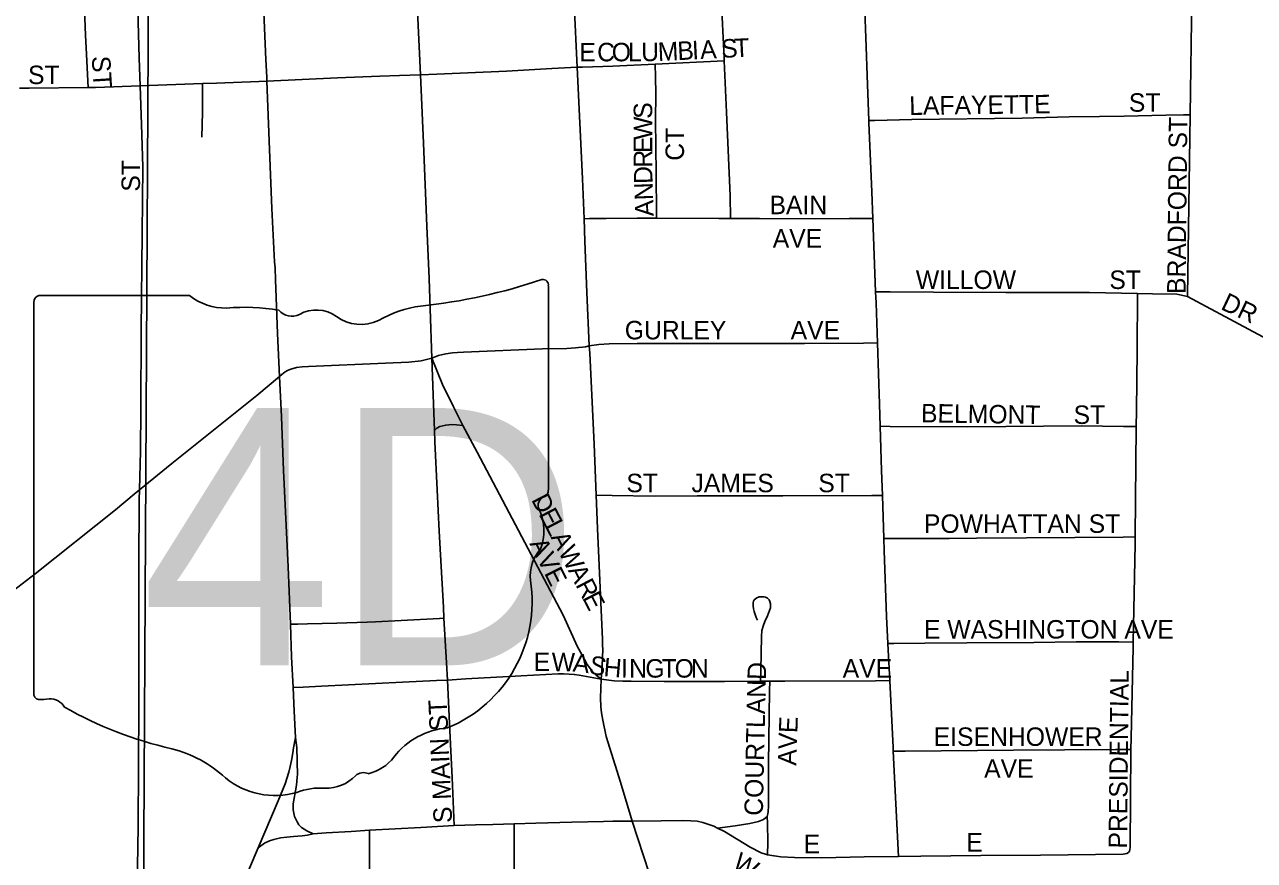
# Model space of a CAD drawing. Extents: x -97 to 34, y -21 to 22.
# Drawn here: x 5.533 to 6.163, y 18.994 to 19.422 of the extents above; entities that cross this region are included whole.
import ezdxf

# ---------------------------------------------------------------- set-up
doc = ezdxf.new("R2010")
doc.units = 0
for name, color, linetype in [('GM_X_City_Street', 7, 'Continuous'), ('GM_X_City_Street_Text', 7, 'Continuous'), ('GM_X_Section', 7, 'Continuous'), ('GM_X_State_Location', 7, 'Continuous'), ('GM_X_State_Route', 7, 'Continuous'), ('GM_X_State_Shield', 7, 'Continuous')]:
    doc.layers.add(name, color=color, linetype=linetype)

msp = doc.modelspace()

# ---------------------------------------------------------------- linework, layer by layer
at = {"layer": 'GM_X_City_Street'}
for points in [[(5.56519, 19.38978), (5.5642, 19.41012), (5.56376, 19.41668), (5.56336, 19.42539), (5.56266, 19.44389), (5.56246, 19.45285)], [(5.59185, 19.39064), (5.59135, 19.40487), (5.59057, 19.42962), (5.5894, 19.45308)], [(5.89109, 19.40348), (5.89103, 19.40499), (5.88954, 19.4362)], [(5.96306, 19.43384), (5.96394, 19.41059), (5.96445, 19.39593), (5.96525, 19.37289)], [(6.1299, 19.37581), (6.13076, 19.43609)], [(5.7355, 19.39632), (5.73394, 19.42898)], [(5.81579, 19.40021), (5.81843, 19.40029), (5.83406, 19.40077), (5.85574, 19.40184)], [(5.85574, 19.40184), (5.89109, 19.40348)], [(5.85648, 19.32277), (5.85648, 19.32516), (5.85621, 19.34582), (5.85587, 19.37305), (5.8561, 19.38656), (5.85598, 19.39532), (5.85574, 19.40184)], [(5.89425, 19.32267), (5.89413, 19.33422), (5.89234, 19.37717), (5.89109, 19.40348)], [(5.65673, 19.39306), (5.6929, 19.39476), (5.71459, 19.39557), (5.7247, 19.39592), (5.7355, 19.39632)], [(5.52997, 19.38945), (5.53485, 19.38947), (5.56519, 19.38978)], [(5.56519, 19.38978), (5.56896, 19.38982), (5.59185, 19.39064)], [(5.59144, 19.1837), (5.59202, 19.20337), (5.59206, 19.22506), (5.59237, 19.2654), (5.59289, 19.31503), (5.59308, 19.34916), (5.59253, 19.37083), (5.59185, 19.39064)], [(5.59185, 19.39064), (5.62367, 19.39178)], [(5.62367, 19.39178), (5.62369, 19.3883), (5.62372, 19.37719), (5.62339, 19.36436)], [(5.62367, 19.39178), (5.63092, 19.39204), (5.65256, 19.39287), (5.65673, 19.39306)], [(5.96525, 19.37289), (5.96837, 19.37297), (5.98725, 19.37341), (6.04383, 19.37409), (6.06782, 19.37477), (6.08337, 19.37489), (6.09614, 19.37517), (6.11745, 19.37561), (6.12655, 19.37576), (6.1299, 19.37581)], [(6.12857, 19.28265), (6.1299, 19.37581)], [(5.96525, 19.37289), (5.96529, 19.37173), (5.96669, 19.3363), (5.96723, 19.32266)], [(5.8194, 19.32247), (5.82211, 19.32272), (5.83062, 19.32264), (5.84648, 19.32279), (5.85648, 19.32277)], [(5.85648, 19.32277), (5.88829, 19.32269), (5.89425, 19.32267)], [(5.89425, 19.32267), (5.90928, 19.32262), (5.93752, 19.32254), (5.95511, 19.32268), (5.96068, 19.32274), (5.96723, 19.32266)], [(5.96723, 19.32266), (5.96872, 19.28504)], [(5.96872, 19.28504), (5.97614, 19.28508), (5.99836, 19.28496), (6.03538, 19.28476), (6.07831, 19.28478), (6.10291, 19.28417)], [(5.96872, 19.28504), (5.96894, 19.27942), (5.96967, 19.25889)], [(6.10231, 19.21604), (6.10245, 19.22412), (6.1027, 19.25519), (6.10291, 19.28417)], [(6.10291, 19.28417), (6.11054, 19.28402), (6.12307, 19.28387), (6.12857, 19.28265)], [(6.12857, 19.28265), (6.15986, 19.26603), (6.18723, 19.25123)], [(5.74132, 19.25111), (5.74462, 19.2525), (5.74838, 19.25332), (5.7519, 19.25384), (5.75447, 19.25401), (5.75753, 19.25423), (5.79795, 19.25586), (5.81048, 19.2561), (5.81496, 19.25638), (5.81646, 19.25653), (5.81844, 19.25672), (5.82007, 19.25694), (5.82195, 19.25734)], [(5.82195, 19.25734), (5.82683, 19.25809), (5.83223, 19.25843), (5.8465, 19.25857), (5.87142, 19.25858), (5.90187, 19.25859), (5.93219, 19.25868), (5.96246, 19.25885), (5.96967, 19.25889)], [(5.96967, 19.25889), (5.97078, 19.2275), (5.97109, 19.21618)], [(5.74259, 19.21403), (5.74197, 19.23231), (5.74132, 19.25111)], [(5.75723, 19.21662), (5.7524, 19.22616), (5.74671, 19.23756), (5.74132, 19.25111)], [(5.74259, 19.21403), (5.74389, 19.21525), (5.74541, 19.21605), (5.74843, 19.21677), (5.75153, 19.21706), (5.75384, 19.21698), (5.75723, 19.21662)], [(5.74743, 19.11781), (5.7472, 19.12355), (5.74569, 19.15037), (5.7451, 19.16248), (5.74407, 19.18357), (5.74287, 19.20823), (5.74259, 19.21403)], [(5.82802, 19.0866), (5.82527, 19.0888), (5.82363, 19.09044), (5.82081, 19.0941), (5.81807, 19.09928), (5.81598, 19.10321), (5.80851, 19.11931), (5.76444, 19.2029), (5.75723, 19.21662)], [(5.97109, 19.21618), (5.97618, 19.21616), (6.01597, 19.21595), (6.07427, 19.21634), (6.09571, 19.216), (6.10231, 19.21604)], [(5.97109, 19.21618), (5.9717, 19.19351), (5.97216, 19.18074)], [(6.10174, 19.15949), (6.10231, 19.21604)], [(5.58975, 18.8933), (5.59013, 18.93041), (5.59013, 18.96145), (5.59029, 18.9801), (5.59084, 19.01111), (5.59091, 19.04212), (5.59113, 19.07316), (5.59112, 19.11343), (5.59118, 19.14442), (5.59129, 19.17858), (5.59144, 19.1837)], [(5.82554, 19.18085), (5.83373, 19.18074), (5.85545, 19.18044), (5.8773, 19.1805), (5.9212, 19.18061), (5.96681, 19.18072), (5.97216, 19.18074)], [(5.97216, 19.18074), (5.97294, 19.15861)], [(5.97294, 19.15861), (5.97872, 19.15864), (5.9972, 19.15872), (6.00636, 19.15867), (6.02049, 19.15879), (6.04599, 19.15901), (6.09553, 19.15943), (6.10174, 19.15949)], [(5.97294, 19.15861), (5.97316, 19.15245), (5.9743, 19.11871), (5.97499, 19.10482)], [(6.10071, 19.10558), (6.10171, 19.15583), (6.10174, 19.15949)], [(5.90972, 19.08548), (5.90992, 19.09118), (5.91022, 19.10853), (5.91042, 19.11148), (5.91124, 19.1143), (5.91193, 19.1161), (5.91326, 19.11901), (5.9144, 19.12182), (5.91478, 19.12315), (5.9149, 19.12403), (5.91482, 19.12524), (5.91454, 19.12631), (5.91417, 19.12719), (5.91337, 19.1281), (5.91227, 19.12864), (5.91146, 19.12879), (5.91015, 19.12885), (5.90905, 19.12871), (5.90775, 19.12825), (5.90709, 19.12778), (5.9065, 19.1272), (5.90615, 19.12655), (5.90593, 19.12579), (5.90589, 19.12425), (5.90616, 19.12271), (5.90652, 19.12122), (5.90698, 19.11966), (5.90755, 19.11817), (5.90821, 19.11684)], [(5.66876, 19.1147), (5.67263, 19.11481), (5.67757, 19.11495), (5.69261, 19.11533), (5.70818, 19.11579), (5.71241, 19.11598), (5.72554, 19.11669), (5.74518, 19.1177), (5.74743, 19.11781)], [(5.74922, 19.08609), (5.74871, 19.09493), (5.74743, 19.11781)], [(5.97499, 19.10482), (5.978, 19.10485), (5.99396, 19.10498), (6.01541, 19.10519), (6.04983, 19.10538), (6.0715, 19.10565), (6.09343, 19.10564), (6.10071, 19.10558)], [(5.97499, 19.10482), (5.97514, 19.1017), (5.97593, 19.08583)], [(6.09956, 19.05046), (6.09961, 19.05646), (6.10066, 19.10284), (6.10071, 19.10558)], [(5.67018, 19.08229), (5.67538, 19.08255), (5.68471, 19.08302), (5.72624, 19.0851), (5.74358, 19.08594), (5.74922, 19.08609)], [(5.74922, 19.08609), (5.75862, 19.08679), (5.78699, 19.08831), (5.80601, 19.08926), (5.80876, 19.08924), (5.81158, 19.08921), (5.81426, 19.08903), (5.81679, 19.08858), (5.82802, 19.0866)], [(5.75266, 19.01158), (5.7517, 19.03623), (5.75093, 19.04969), (5.75032, 19.06388), (5.74922, 19.08609)], [(5.82802, 19.0866), (5.8347, 19.08579), (5.83922, 19.0855), (5.8435, 19.08548), (5.86034, 19.08544), (5.89126, 19.08543), (5.90972, 19.08548)], [(5.90972, 19.08548), (5.91447, 19.0855)], [(5.91305, 19.01622), (5.91353, 19.01759), (5.91372, 19.01876), (5.91376, 19.02148), (5.91387, 19.04317), (5.9144, 19.08067), (5.91447, 19.0855)], [(5.91447, 19.0855), (5.92214, 19.08553), (5.96861, 19.08578), (5.97593, 19.08583)], [(5.97593, 19.08583), (5.97763, 19.05163), (5.97773, 19.04969)], [(5.97773, 19.04969), (5.98388, 19.04975), (6.03929, 19.05023), (6.09162, 19.05055), (6.0947, 19.05051), (6.09956, 19.05046)], [(5.97773, 19.04969), (5.9805, 18.9957)], [(6.0983, 18.99774), (6.09876, 18.9984), (6.09905, 18.99929), (6.09917, 19.0003), (6.09956, 19.05046)], [(5.88769, 19.0103), (5.89667, 19.01148), (5.90418, 19.01263), (5.90862, 19.01356), (5.91133, 19.01471), (5.91305, 19.01622)], [(5.91334, 18.99662), (5.91344, 19.0029), (5.91325, 19.01286), (5.91305, 19.01622)], [(5.70943, 18.88967), (5.70942, 18.91883), (5.70936, 18.98514), (5.70929, 19.00356), (5.70936, 19.00915)], [(5.78232, 18.84388), (5.78273, 18.89006), (5.78335, 18.91997), (5.78339, 18.93672), (5.78344, 18.9592), (5.78347, 18.98194), (5.78344, 19.0038), (5.78338, 19.01248)], [(5.88769, 19.0103), (5.88585, 19.01123), (5.88018, 19.0131), (5.87718, 19.01378), (5.87398, 19.01407), (5.86971, 19.01416), (5.85886, 19.01403), (5.84391, 19.01387)], [(5.91334, 18.99662), (5.91278, 18.99671), (5.9101, 18.99765), (5.90438, 19.00042), (5.89126, 19.0085), (5.88769, 19.0103)], [(5.9805, 18.9957), (5.96289, 18.99558), (5.94118, 18.99508), (5.92716, 18.99524), (5.92014, 18.99557), (5.91668, 18.99601), (5.91334, 18.99662)], [(5.9805, 18.9957), (5.99195, 18.9959), (6.02255, 18.99616), (6.05317, 18.9964), (6.09561, 18.99691), (6.09647, 18.99699), (6.09741, 18.99719), (6.0983, 18.99774)]]:
    msp.add_lwpolyline(points, dxfattribs=at)
at = {"layer": 'GM_X_Section'}
for points in [[(4.59865, 19.47855), (5.59615, 19.47364), (5.59082, 18.47236), (4.59557, 18.47233)], [(5.59615, 19.47364), (6.60805, 19.46219), (6.59547, 18.46625), (5.59082, 18.47236)]]:
    msp.add_lwpolyline(points, close=True, dxfattribs=at)
at = {"layer": 'GM_X_State_Route'}
for points in [[(5.81579, 19.40021), (5.81426, 19.43276), (5.81368, 19.44493), (5.81305, 19.46133), (5.81178, 19.49422), (5.81007, 19.53664), (5.80859, 19.57918)], [(5.64841, 19.57304), (5.65021, 19.54453), (5.65196, 19.49769), (5.65352, 19.46651), (5.65397, 19.45497), (5.65413, 19.45102), (5.65492, 19.4323), (5.65622, 19.40416), (5.65663, 19.39506)], [(5.7355, 19.39632), (5.74385, 19.39671), (5.77947, 19.39823), (5.80271, 19.39949), (5.81579, 19.40021)], [(5.82883, 19.10163), (5.82881, 19.10422), (5.82878, 19.10697), (5.82625, 19.16379), (5.82554, 19.18085), (5.82444, 19.20711), (5.82223, 19.25365), (5.82195, 19.25734), (5.82075, 19.28483), (5.81976, 19.3111), (5.8194, 19.32247), (5.81849, 19.34306), (5.81579, 19.40021)], [(5.65663, 19.39506), (5.65673, 19.39306), (5.65802, 19.35803), (5.65931, 19.32772), (5.66071, 19.30046), (5.6609, 19.29743), (5.66111, 19.29131), (5.66157, 19.28214), (5.66213, 19.26381), (5.66316, 19.24175)], [(5.74132, 19.25111), (5.74041, 19.27633), (5.73985, 19.29189), (5.73874, 19.31883), (5.73698, 19.36137), (5.7355, 19.39632)], [(5.52685, 19.132), (5.53798, 19.14055), (5.57916, 19.17341), (5.58864, 19.18142), (5.59144, 19.1837), (5.60795, 19.19715), (5.62255, 19.20881), (5.65162, 19.23203), (5.66316, 19.24175), (5.66447, 19.24281), (5.66604, 19.24406), (5.66728, 19.24477), (5.66902, 19.24541), (5.67196, 19.24624), (5.67488, 19.2467), (5.67804, 19.24675), (5.7175, 19.24848), (5.72944, 19.24908), (5.73576, 19.24977), (5.74132, 19.25111)], [(5.66316, 19.24175), (5.66424, 19.22098), (5.66521, 19.19356), (5.66756, 19.14419), (5.66876, 19.1147), (5.66943, 19.09796), (5.67018, 19.08229), (5.67076, 19.07019), (5.67148, 19.05665)], [(5.82802, 19.0866), (5.8285, 19.09305), (5.82875, 19.09802), (5.82883, 19.10158), (5.82883, 19.10163)], [(5.84391, 19.01387), (5.8379, 19.03376), (5.83054, 19.05721), (5.82883, 19.06566), (5.82825, 19.06942), (5.82793, 19.0724), (5.8277, 19.07702), (5.82802, 19.0866)], [(5.67148, 19.05665), (5.67043, 19.05141), (5.67004, 19.04887), (5.66934, 19.04485), (5.66871, 19.04179), (5.66798, 19.03888), (5.66613, 19.03295), (5.66259, 19.02428), (5.6523, 19.00021)], [(5.67148, 19.05665), (5.67202, 19.05156), (5.67237, 19.03746), (5.67233, 19.03672), (5.67203, 19.03375), (5.67166, 19.0312), (5.67015, 19.02266), (5.6702, 19.01967), (5.67084, 19.01629), (5.67223, 19.01339), (5.67319, 19.01201), (5.67447, 19.01057), (5.67726, 19.0089), (5.68042, 19.00736)], [(5.68042, 19.00736), (5.68704, 19.00778), (5.69989, 19.00857), (5.70936, 19.00915), (5.73562, 19.01063), (5.75266, 19.01158), (5.76364, 19.0119), (5.77247, 19.01216), (5.78338, 19.01248), (5.79463, 19.01278), (5.81302, 19.01326), (5.82918, 19.01369), (5.83408, 19.01382), (5.84391, 19.01387)], [(5.95066, 18.68279), (5.9491, 18.68751), (5.94556, 18.69846), (5.93346, 18.73675), (5.91921, 18.78107), (5.90309, 18.83106), (5.89819, 18.84638), (5.87475, 18.9197), (5.8651, 18.94911), (5.85832, 18.96965), (5.85266, 18.98722), (5.84391, 19.01387)], [(5.6523, 19.00021), (5.65543, 19.00254), (5.65802, 19.0037), (5.66025, 19.0045), (5.66373, 19.00521), (5.66703, 19.00558), (5.67044, 19.00589), (5.6748, 19.00629), (5.67754, 19.00666), (5.68042, 19.00736)], [(5.64341, 18.97929), (5.6523, 19.00021)]]:
    msp.add_lwpolyline(points, dxfattribs=at)
at = {"layer": 'GM_X_State_Shield'}
for p, q in [((5.80099, 19.18342), (5.80099, 19.28811)), ((5.61713, 19.28315), (5.53992, 19.28315)), ((5.53732, 19.27971), (5.53732, 19.07959)), ((5.80096, 19.18345), (5.80099, 19.18342))]:
    msp.add_line(p, q, dxfattribs=at)
for centre, radius, start, end in [((5.70707, 19.55598), 0.27962, 275.84447, 288.90645), ((5.79806, 19.28854), 0.00294, 351.86209, 97.738), ((5.54034, 19.28013), 0.00305, 98.1301, 188.1301), ((5.63552, 19.30638), 0.02963, 231.61951, 271.11188), ((5.64535, 19.1708), 0.10636, 80.48669, 94.98827), ((5.66949, 19.28117), 0.00855, 219.79206, 297.10237), ((5.68204, 19.25804), 0.01777, 54.46668, 119.14113), ((5.74273, 19.22203), 0.05625, 97.34618, 120.76885), ((5.70498, 19.28976), 0.02138, 233.85621, 294.82819), ((5.80031, 19.17574), 0.00454, 107.94398, 210.33697), ((5.79786, 19.18302), 0.00314, 289.60381, 7.73413), ((5.77141, 19.16251), 0.02727, 340.03296, 23.64957), ((5.81151, 19.13961), 0.01984, 136.8065, 186.92959), ((5.72273, 19.1263), 0.06994, 292.30889, 8.98584), ((5.54037, 19.07915), 0.00308, 171.95839, 258.30661), ((5.54084, 19.09962), 0.02352, 267.33899, 280.60386), ((5.54565, 19.06804), 0.00848, 29.74838, 93.27175), ((5.65271, 19.24784), 0.20192, 240.41292, 257.1985), ((5.75222, 19.0234), 0.0383, 94.40312, 142.57675), ((5.59251, 18.98968), 0.06318, 47.18416, 75.83597), ((5.70369, 19.06019), 0.0226, 282.87319, 323.27711), ((5.66084, 19.06705), 0.04009, 230.70037, 286.29184), ((5.68693, 19.05206), 0.02136, 268.77702, 315.54927), ((5.70625, 19.03268), 0.00601, 65.75173, 132.64842), ((5.684, 18.99786), 0.03294, 85.69512, 111.20995)]:
    msp.add_arc(centre, radius, start, end, dxfattribs=at)

# ---------------------------------------------------------------- texts
at = {"layer": 'GM_X_City_Street_Text'}
for s, height, rotation, p in [('E', 0.00947, 0.02732, (5.81683, 19.40323)), ('C', 0.00947, 0.0178, (5.826, 19.40323)), ('O', 0.00947, 0.01536, (5.83349, 19.40324)), ('L', 0.00947, 0.02058, (5.84183, 19.40324)), ('U', 0.00947, 0.6462, (5.84861, 19.40324)), ('M', 0.00947, 2.63197, (5.85729, 19.40335)), ('B', 0.00947, 2.9268, (5.86734, 19.40381)), ('I', 0.00947, 2.88642, (5.87483, 19.40419)), ('A', 0.00947, 2.90186, (5.87899, 19.4044)), ('S', 0.00947, 2.90372, (5.88981, 19.40495)), ('T', 0.00947, 2.89789, (5.89647, 19.40529)), ('ST', 0.00947, 0.00001, (5.53433, 19.39156)), ('ST', 0.00947, 273.57465, (5.56694, 19.40572)), ('S', 0.00947, 90, (5.85421, 19.37377)), ('LAFAYETTE', 0.00947, 0.71578, (5.98597, 19.37573)), ('ST', 0.00947, 0.00001, (6.09849, 19.37739)), ('W', 0.00947, 90, (5.85421, 19.36294)), ('CT', 0.00947, 90, (5.8705, 19.35228)), ('BRADFORD ST', 0.0094697, 89.39724, (6.12754, 19.28396)), ('E', 0.00947, 90, (5.85421, 19.35627)), ('R', 0.00947, 90.07288, (5.85422, 19.34877)), ('ST', 0.00947, 90, (5.59171, 19.33644)), ('D', 0.00947, 91.3551, (5.85442, 19.3405)), ('N', 0.00947, 92.19047, (5.85473, 19.33221)), ('A', 0.00947, 92.16397, (5.85505, 19.32387)), ('BAIN', 0.00947, 0.00001, (5.91433, 19.32489)), ('AVE', 0.00947, 0.00001, (5.91599, 19.30777)), ('WILLOW', 0.00947, 0.00001, (5.98932, 19.28656)), ('ST', 0.00947, 0.00001, (6.08849, 19.28656)), ('DR', 0.00947, 334.80321, (6.14508, 19.27639)), ('GURLEY', 0.00947, 0.00001, (5.84016, 19.26073)), ('AVE', 0.00947, 0.00001, (5.92516, 19.26073)), ('BELMONT', 0.00947, 359.14642, (5.99193, 19.21823)), ('ST', 0.00947, 0.00001, (6.07016, 19.2174)), ('ST', 0.00947, 0.00001, (5.84099, 19.18239)), ('JAMES', 0.00947, 0.00001, (5.87433, 19.18239)), ('ST', 0.00947, 0.00001, (5.93933, 19.18239)), ('D', 0.00947, 297.46435, (5.79203, 19.1786)), ('E', 0.00947, 297.45698, (5.79588, 19.1712)), ('L', 0.00947, 297.47568, (5.79895, 19.16528)), ('POWHATTAN ST', 0.0094697, 0.00001, (5.99349, 19.16156)), ('A', 0.00947, 297.46435, (5.80203, 19.15937)), ('AVE', 0.00947, 296.56506, (5.79109, 19.15608)), ('W', 0.00947, 297.46728, (5.80587, 19.15198)), ('A', 0.00947, 297.46435, (5.81087, 19.14236)), ('R', 0.00947, 297.46668, (5.81471, 19.13497)), ('E', 0.00947, 297.45698, (5.81817, 19.12832)), ('E WASHINGTON AVE', 0.0094697, 0.00001, (5.99349, 19.1074)), ('E', 0.00947, 0.00001, (5.79349, 19.09073)), ('W', 0.00947, 359.14239, (5.80262, 19.09073)), ('A', 0.00947, 353.60429, (5.81321, 19.09058)), ('S', 0.00947, 348.13808, (5.82126, 19.08969)), ('H', 0.00947, 355.27387, (5.82905, 19.08814)), ('I', 0.00947, 359.81967, (5.83817, 19.08741)), ('N', 0.00947, 359.94784, (5.84237, 19.0874)), ('G', 0.00947, 359.99285, (5.85071, 19.08739)), ('T', 0.00947, 359.99563, (5.85904, 19.08739)), ('O', 0.00947, 359.99285, (5.86571, 19.08739)), ('N', 0.00947, 359.99285, (5.87404, 19.08739)), ('COURTLAND', 0.00947, 88.6943, (5.91087, 19.0165)), ('AVE', 0.00947, 0.00001, (5.95183, 19.08739)), ('PRESIDENTIAL', 0.0094697, 89.41225, (6.09754, 18.99975)), ('S MAIN ST', 0.00947, 92.52806, (5.75171, 19.01304)), ('E', 0.00947, 87.98296, (5.92858, 19.05885)), ('EISENHOWER', 0.00947, 0.00001, (5.99849, 19.05239)), ('V', 0.00947, 87.94522, (5.92828, 19.05052)), ('A', 0.00947, 88.09812, (5.928, 19.0422)), ('AVE', 0.00947, 0.00001, (6.02433, 19.0361)), ('E', 0.00947, 0.00001, (5.93183, 18.99739)), ('E', 0.00947, 0.00001, (6.01516, 18.99823)), ('W', 0.00947, 328.82865, (5.8947, 18.99015))]:
    msp.add_text(s, height=height, rotation=rotation, dxfattribs=at).set_placement(p)
at = {"layer": 'GM_X_State_Location'}
for s in ['s', 'r']:
    msp.add_text(s, height=0.000189, dxfattribs=at).set_placement((5.66618, 19.16634))
msp.add_text('4D', height=0.000189, rotation=0.00001, dxfattribs=at).set_placement((5.61266, 19.15256))
at = {"layer": 'GM_X_State_Shield'}
msp.add_text('4D', height=0.131836, dxfattribs=at).set_placement((5.59214, 19.0937))

doc.saveas('drawing.dxf')
